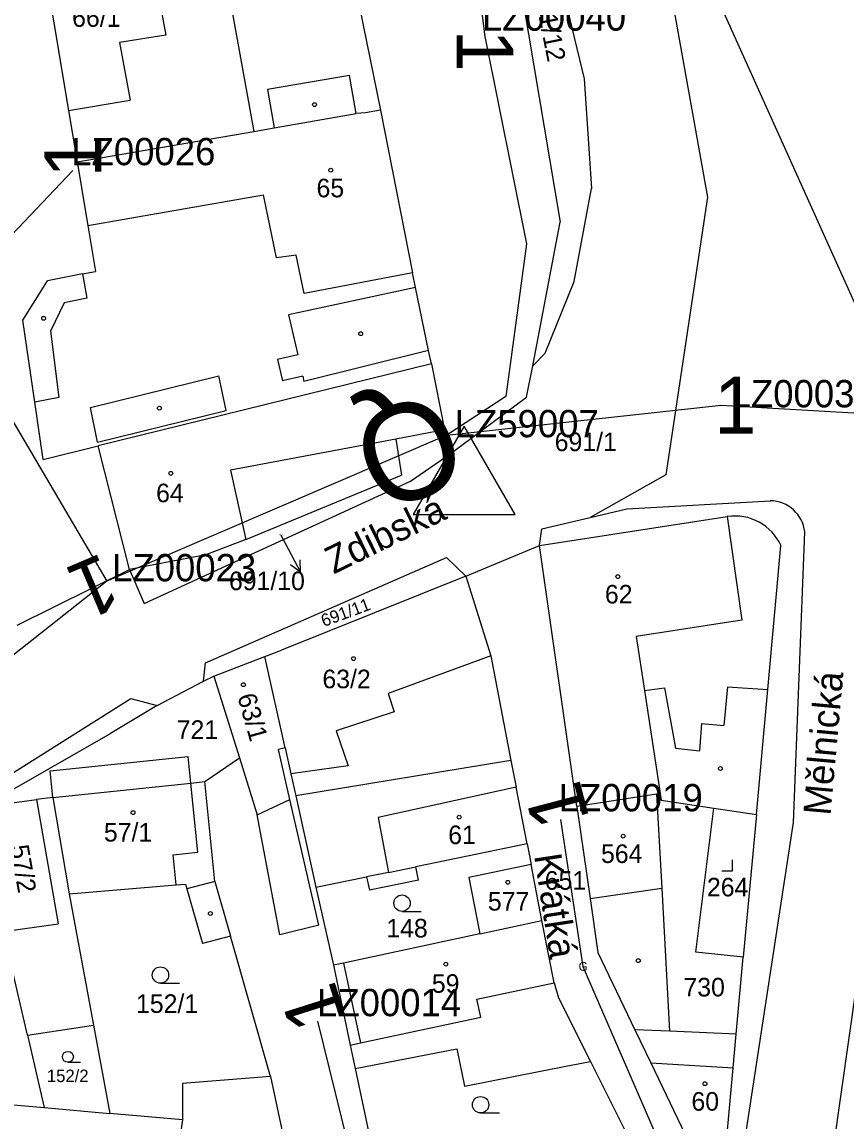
# Model space of a CAD drawing. Extents: x -738131 to -734179, y -1033447 to -1030078.
# Drawn here: x -736144.6 to -736069.2, y -1032267.7 to -1032166.9 of the extents above; entities that cross this region are included whole.
import ezdxf

# ---------------------------------------------------------------- set-up
doc = ezdxf.new("R2010")
doc.units = 0
for name, color, linetype in [('ftf_2010', 7, 'Continuous'), ('ftf_2050', 7, 'Continuous'), ('ftf_2080', 7, 'Continuous'), ('ftf_2240', 7, 'Continuous'), ('ftf_3010', 7, 'Continuous'), ('ftf_3010_ftf_3010_gtda_3015_gtda_3015_1', 7, 'Continuous'), ('ftf_3240', 7, 'Continuous'), ('ftf_3260', 7, 'Continuous'), ('ftf_3260_ftf_3260_gtda_3265_gtda_3265_1', 7, 'Continuous'), ('ftf_nu', 7, 'Continuous'), ('Vrstva 1', 7, 'Continuous'), ('Vrstva 2', 7, 'Continuous'), ('Vrstva 3', 7, 'Continuous'), ('Vrstva 4', 7, 'Continuous'), ('Vrstva 5', 7, 'Continuous'), ('Vrstva 7', 7, 'Continuous')]:
    doc.layers.add(name, color=color, linetype=linetype)

msp = doc.modelspace()

# ---------------------------------------------------------------- linework, layer by layer
at = {"layer": 'ftf_2010'}
for points in [[(-736107.59, -1032126.1), (-736102.25, -1032168.26)], [(-736102.25, -1032168.26), (-736098.43, -1032187.26), (-736100.35, -1032201.22), (-736105.73, -1032204.76)]]:
    msp.add_lwpolyline(points, dxfattribs=at)
at = {"layer": 'ftf_2050'}
for points in [[(-736169.66, -1032178.44), (-736151.73, -1032192.91), (-736136.87, -1032218.15)], [(-736139.99, -1032180.53), (-736151.73, -1032192.91)], [(-736105.73, -1032204.76), (-736080.61, -1032202.02)], [(-736080.61, -1032202.02), (-736059.51, -1032203.25)], [(-736136.87, -1032218.15), (-736162, -1032237.98)], [(-736095.33, -1032239.95), (-736093.27, -1032253.41), (-736082.77, -1032277.61)], [(-736117.59, -1032258.43), (-736105.13, -1032308.95)]]:
    msp.add_lwpolyline(points, dxfattribs=at)
at = {"layer": 'ftf_2080'}
msp.add_lwpolyline([(-736105.73, -1032204.76), (-736136.87, -1032218.15)], dxfattribs=at)
at = {"layer": 'ftf_2240'}
msp.add_lwpolyline([(-736108.82, -1032212.03), (-736099.47, -1032212.03), (-736104.14, -1032203.93)], close=True, dxfattribs=at)
at = {"layer": 'Vrstva 1'}
for points in [[(-736101.65, -1032147.92), (-736095.37, -1032185.27)], [(-736087.87, -1032149.39), (-736081.88, -1032182.97)], [(-736087.87, -1032149.39), (-736067.88, -1032193.8)], [(-736096.91, -1032156.59), (-736093.17, -1032172.14)], [(-736143.06, -1032158.95), (-736140.37, -1032175.05)], [(-736115.01, -1032159.26), (-736111.82, -1032175.01)], [(-736125.82, -1032163.63), (-736123.41, -1032176.95)], [(-736093.17, -1032172.14), (-736092.5, -1032182.19)], [(-736140.37, -1032175.05), (-736139.59, -1032179.75)], [(-736111.82, -1032175.01), (-736113.19, -1032175.26)], [(-736111.82, -1032175.01), (-736108.88, -1032189.89)], [(-736121.56, -1032176.63), (-736114.04, -1032175.33)], [(-736113.19, -1032175.26), (-736114.04, -1032175.33)], [(-736139.59, -1032179.75), (-736123.41, -1032176.95)], [(-736123.41, -1032176.95), (-736121.56, -1032176.63)], [(-736139.59, -1032179.75), (-736138.62, -1032185.57)], [(-736094.08, -1032190.71), (-736092.5, -1032182.19)], [(-736081.88, -1032182.97), (-736085.67, -1032208.4)], [(-736097.87, -1032198.41), (-736095.37, -1032185.27)], [(-736138.62, -1032185.57), (-736137.92, -1032189.77)], [(-736139.1, -1032190), (-736142.32, -1032190.63)], [(-736139.1, -1032190), (-736137.92, -1032189.77)], [(-736108.6, -1032191.24), (-736108.88, -1032189.89)], [(-736144.57, -1032194.23), (-736142.32, -1032190.63)], [(-736107.41, -1032197.01), (-736108.6, -1032191.24)], [(-736096.74, -1032197.25), (-736094.08, -1032190.71)], [(-736143.47, -1032201.74), (-736144.57, -1032194.23)], [(-736107.15, -1032198.24), (-736107.41, -1032197.01)], [(-736097.87, -1032198.41), (-736096.74, -1032197.25)], [(-736107.15, -1032198.24), (-736137.65, -1032205.75)], [(-736107.15, -1032198.24), (-736105.96, -1032204.29)], [(-736098.44, -1032201.3), (-736097.87, -1032198.41)], [(-736105.42, -1032206.49), (-736098.44, -1032201.3)], [(-736142.7, -1032207), (-736143.47, -1032201.74)], [(-736105.96, -1032204.29), (-736110.41, -1032205.12)], [(-736105.96, -1032204.29), (-736105.42, -1032206.49)], [(-736110.41, -1032205.12), (-736109.88, -1032208.43)], [(-736142.7, -1032207), (-736137.65, -1032205.75)], [(-736134.79, -1032217.08), (-736137.65, -1032205.75)], [(-736109.06, -1032208.99), (-736105.42, -1032206.49)], [(-736124.13, -1032214.32), (-736109.88, -1032208.43)], [(-736085.67, -1032208.4), (-736092.61, -1032212.3)], [(-736133.44, -1032220.19), (-736109.06, -1032208.99)], [(-736089.27, -1032211.52), (-736076.11, -1032210.77)], [(-736097.24, -1032214.86), (-736080.07, -1032212.23)], [(-736097.03, -1032213.33), (-736092.61, -1032212.3)], [(-736092.61, -1032212.3), (-736089.27, -1032211.52)], [(-736097.24, -1032214.86), (-736097.03, -1032213.33)], [(-736124.13, -1032214.32), (-736127.82, -1032215.73)], [(-736073.98, -1032240.24), (-736072.95, -1032213.63)], [(-736104, -1032217.69), (-736097.24, -1032214.86)], [(-736093.82, -1032238.76), (-736097.24, -1032214.86)], [(-736076.34, -1032228.05), (-736075.14, -1032214.9)], [(-736127.82, -1032215.73), (-736134.79, -1032217.08)], [(-736127.84, -1032225.62), (-736105.77, -1032215.97)], [(-736105.77, -1032215.97), (-736104, -1032217.69)], [(-736145.07, -1032222.16), (-736134.79, -1032217.08)], [(-736134.79, -1032217.08), (-736133.44, -1032220.19)], [(-736104, -1032217.69), (-736120.89, -1032224.44)], [(-736104, -1032217.69), (-736101.72, -1032224.97)], [(-736122.41, -1032225.03), (-736120.89, -1032224.44)], [(-736127.07, -1032226.83), (-736122.41, -1032225.03)], [(-736120.55, -1032233.41), (-736122.41, -1032225.03)], [(-736101.72, -1032224.97), (-736099.87, -1032234.55)], [(-736128.02, -1032227.3), (-736127.84, -1032225.62)], [(-736132.25, -1032229.51), (-736128.02, -1032227.3)], [(-736128.02, -1032227.3), (-736127.07, -1032226.83)], [(-736127.07, -1032226.83), (-736124.73, -1032234.32)], [(-736077.39, -1032239.5), (-736076.34, -1032228.05)], [(-736148.25, -1032237.42), (-736134.66, -1032228.89)], [(-736132.25, -1032229.51), (-736136.55, -1032232.07)], [(-736134.66, -1032228.89), (-736132.25, -1032229.51)], [(-736148.3, -1032238.81), (-736136.55, -1032232.07)], [(-736120.55, -1032233.41), (-736121.16, -1032233.54)], [(-736120.11, -1032238.12), (-736121.16, -1032233.54)], [(-736120.55, -1032233.41), (-736120.03, -1032235.78)], [(-736142.06, -1032235.49), (-736129.43, -1032234.18)], [(-736129.18, -1032236.62), (-736129.43, -1032234.18)], [(-736127.89, -1032236.49), (-736124.73, -1032234.32)], [(-736124.73, -1032234.32), (-736123.11, -1032239.52)], [(-736099.87, -1032234.55), (-736119.58, -1032237.8)], [(-736099.87, -1032234.55), (-736099.39, -1032237)], [(-736141.81, -1032237.93), (-736142.06, -1032235.49)], [(-736129.18, -1032236.62), (-736127.89, -1032236.49)], [(-736126.97, -1032245.64), (-736127.89, -1032236.49)], [(-736120.03, -1032235.78), (-736119.58, -1032237.8)], [(-736098.39, -1032242.2), (-736099.39, -1032237)], [(-736086.53, -1032237.64), (-736093.82, -1032238.76)], [(-736086.19, -1032237.59), (-736086.53, -1032237.64)], [(-736086.53, -1032237.64), (-736086.06, -1032246.26)], [(-736086.19, -1032237.59), (-736086.1, -1032238.18)], [(-736148.3, -1032238.81), (-736143.3, -1032238.13)], [(-736141.81, -1032237.93), (-736143.3, -1032238.13)], [(-736141.81, -1032237.93), (-736140.32, -1032246.76)], [(-736117.46, -1032249.62), (-736120.11, -1032238.12)], [(-736119.58, -1032237.8), (-736117.72, -1032246.17)], [(-736086.1, -1032238.18), (-736081.28, -1032238.91)], [(-736121.03, -1032250.52), (-736123.11, -1032239.52)], [(-736093.82, -1032238.76), (-736092.61, -1032247.19)], [(-736082.93, -1032252.1), (-736081.28, -1032238.91)], [(-736081.28, -1032238.91), (-736077.39, -1032239.5)], [(-736077.39, -1032239.5), (-736078.59, -1032252.55)], [(-736078.41, -1032269.16), (-736073.98, -1032240.24)], [(-736098.39, -1032242.2), (-736108.58, -1032244.29)], [(-736098.39, -1032242.2), (-736098.01, -1032244.09)], [(-736108.33, -1032245.51), (-736108.58, -1032244.29)], [(-736098.01, -1032244.09), (-736103.73, -1032245.27)], [(-736097.05, -1032249.22), (-736098.01, -1032244.09)], [(-736126.97, -1032245.64), (-736125.54, -1032250.64)], [(-736117.72, -1032246.17), (-736113.08, -1032245.21)], [(-736113.08, -1032245.21), (-736112.83, -1032246.44)], [(-736108.33, -1032245.51), (-736112.83, -1032246.44)], [(-736103.73, -1032245.27), (-736102.73, -1032250.44)], [(-736071.04, -1032274.99), (-736066.8, -1032245.12)], [(-736140.32, -1032246.76), (-736130.51, -1032245.94)], [(-736140.32, -1032246.76), (-736138.09, -1032258.78)], [(-736130.51, -1032245.94), (-736129.66, -1032245.87)], [(-736129.66, -1032245.87), (-736129.54, -1032246.3)], [(-736129.54, -1032246.3), (-736128.1, -1032251.31)], [(-736117.72, -1032246.17), (-736116.13, -1032253.31)], [(-736086.06, -1032246.26), (-736085.34, -1032259.35)], [(-736092.61, -1032247.19), (-736091.9, -1032252.15)], [(-736117.46, -1032249.62), (-736121.03, -1032250.52)], [(-736102.73, -1032250.44), (-736097.05, -1032249.22)], [(-736095.92, -1032254.9), (-736097.05, -1032249.22)], [(-736144.13, -1032259.71), (-736146.33, -1032250.2)], [(-736125.54, -1032250.64), (-736128.1, -1032251.31)], [(-736121.87, -1032263.48), (-736125.54, -1032250.64)], [(-736102.73, -1032250.44), (-736115.2, -1032253.12)], [(-736091.9, -1032252.15), (-736088.51, -1032259.22)], [(-736078.59, -1032252.55), (-736082.93, -1032252.1)], [(-736079.24, -1032259.61), (-736078.59, -1032252.55)], [(-736115.2, -1032253.12), (-736116.13, -1032253.31)], [(-736116.13, -1032253.31), (-736114.58, -1032260.61)], [(-736095.92, -1032254.9), (-736095.51, -1032256.29)], [(-736095.51, -1032256.29), (-736092.59, -1032262.11)], [(-736144.13, -1032259.71), (-736138.09, -1032258.78)], [(-736138.09, -1032258.78), (-736136.59, -1032266.88)], [(-736144.13, -1032259.71), (-736142.62, -1032266.34)], [(-736085.34, -1032259.35), (-736088.51, -1032259.22)], [(-736088.51, -1032259.22), (-736087.06, -1032262.23)], [(-736079.24, -1032259.61), (-736085.34, -1032259.35)], [(-736079.52, -1032262.7), (-736079.24, -1032259.61)], [(-736114.58, -1032260.61), (-736114.12, -1032262.77)], [(-736114.12, -1032262.77), (-736104.83, -1032260.97)], [(-736104.83, -1032260.97), (-736104.11, -1032264.38)], [(-736114.12, -1032262.77), (-736110.95, -1032277.74)], [(-736104.11, -1032264.38), (-736094.85, -1032262.56)], [(-736094.85, -1032262.56), (-736092.59, -1032262.11)], [(-736092.59, -1032262.11), (-736088.48, -1032270.29)], [(-736087.06, -1032262.23), (-736083.88, -1032268.86)], [(-736080.1, -1032269.07), (-736079.52, -1032262.7)], [(-736121.87, -1032263.48), (-736129.94, -1032264.13)], [(-736121.87, -1032263.48), (-736120.47, -1032270.07)], [(-736129.94, -1032264.13), (-736129.94, -1032267.47)], [(-736154.87, -1032265.25), (-736142.62, -1032266.34)], [(-736142.62, -1032266.34), (-736136.59, -1032266.88)], [(-736129.94, -1032267.47), (-736136.59, -1032266.88)], [(-736129.94, -1032267.47), (-736130.34, -1032270.1)]]:
    msp.add_lwpolyline(points, dxfattribs=at)
for centre, radius, start, end in [((-736076.18, -1032214.02), 3.25, 6.8547, 88.8511), ((-736079.36, -1032216.81), 4.64, 24.359, 98.7626)]:
    msp.add_arc(centre, radius, start, end, dxfattribs=at)
at = {"layer": 'Vrstva 3'}
for p, q in [((-736079.57, -1032244.66), (-736079.57, -1032243.66)), ((-736080.57, -1032244.66), (-736079.57, -1032244.66)), ((-736109.84, -1032248.37), (-736108.09, -1032248.37)), ((-736131.96, -1032254.95), (-736130.21, -1032254.95)), ((-736140.45, -1032262.19), (-736139.27, -1032262.19)), ((-736102.65, -1032266.83), (-736100.9, -1032266.83))]:
    msp.add_line(p, q, dxfattribs=at)
for centre, radius in [((-736109.84, -1032247.62), 0.75), ((-736131.96, -1032254.2), 0.75), ((-736140.44, -1032261.69), 0.503), ((-736102.65, -1032266.08), 0.75)]:
    msp.add_circle(centre, radius, dxfattribs=at)
at = {"layer": 'Vrstva 4'}
for points in [[(-736132.11, -1032164.65), (-736131.48, -1032168.13)], [(-736131.48, -1032168.13), (-736135.71, -1032168.81)], [(-736135.71, -1032168.81), (-736134.75, -1032174.08)], [(-736114.65, -1032171.83), (-736122.16, -1032173.11)], [(-736114.04, -1032175.33), (-736114.65, -1032171.83)], [(-736122.16, -1032173.11), (-736121.56, -1032176.63)], [(-736140.37, -1032175.05), (-736134.75, -1032174.08)], [(-736138.62, -1032185.57), (-736122.53, -1032182.75)], [(-736121.35, -1032188.53), (-736122.53, -1032182.75)], [(-736119.52, -1032188.28), (-736121.35, -1032188.53)], [(-736118.8, -1032191.81), (-736119.52, -1032188.28)], [(-736139.1, -1032190), (-736138.71, -1032192.22)], [(-736108.88, -1032189.89), (-736118.8, -1032191.81)], [(-736108.6, -1032191.24), (-736120.23, -1032193.76)], [(-736138.71, -1032192.22), (-736140.77, -1032192.64)], [(-736140.77, -1032192.64), (-736142.03, -1032195.25)], [(-736120.23, -1032193.76), (-736119.38, -1032197.41)], [(-736142.03, -1032195.25), (-736141.27, -1032201.32)], [(-736119.38, -1032197.41), (-736121.23, -1032197.84)], [(-736107.41, -1032197.01), (-736118.82, -1032199.85)], [(-736121.23, -1032197.84), (-736120.78, -1032199.79)], [(-736138.38, -1032202.22), (-736126.63, -1032199.33)], [(-736125.93, -1032202.51), (-736126.63, -1032199.33)], [(-736118.93, -1032199.36), (-736120.78, -1032199.79)], [(-736118.93, -1032199.36), (-736118.82, -1032199.85)], [(-736141.27, -1032201.32), (-736143.47, -1032201.74)], [(-736137.72, -1032205.41), (-736138.38, -1032202.22)], [(-736137.72, -1032205.41), (-736125.93, -1032202.51)], [(-736110.41, -1032205.12), (-736125.54, -1032207.98)], [(-736125.54, -1032207.98), (-736124.13, -1032214.32)], [(-736080.07, -1032212.23), (-736078.71, -1032221.72)], [(-736078.71, -1032221.72), (-736088.39, -1032223.2)], [(-736088.39, -1032223.2), (-736087.63, -1032228.16)], [(-736101.72, -1032224.97), (-736111.1, -1032228.43)], [(-736111.1, -1032228.43), (-736110.56, -1032230.09)], [(-736087.63, -1032228.16), (-736085.8, -1032227.89)], [(-736087.63, -1032228.16), (-736086.19, -1032237.59)], [(-736085.8, -1032227.89), (-736084.81, -1032233.43)], [(-736080.05, -1032227.8), (-736080.38, -1032231.36)], [(-736080.05, -1032227.8), (-736076.34, -1032228.05)], [(-736110.56, -1032230.09), (-736115.88, -1032231.84)], [(-736082.43, -1032231.17), (-736082.6, -1032233.68)], [(-736082.43, -1032231.17), (-736080.38, -1032231.36)], [(-736115.88, -1032231.84), (-736114.78, -1032235.06)], [(-736084.81, -1032233.43), (-736082.6, -1032233.68)], [(-736114.78, -1032235.06), (-736120.03, -1032235.78)], [(-736141.81, -1032237.93), (-736129.18, -1032236.62)], [(-736128.53, -1032242.95), (-736129.18, -1032236.62)], [(-736099.39, -1032237), (-736112.04, -1032239.77)], [(-736143.3, -1032238.13), (-736141.33, -1032249.52)], [(-736123.11, -1032239.52), (-736120.11, -1032238.12)], [(-736112.04, -1032239.77), (-736111.07, -1032244.8)], [(-736130.79, -1032243.18), (-736128.53, -1032242.95)], [(-736130.51, -1032245.94), (-736130.79, -1032243.18)], [(-736111.07, -1032244.8), (-736108.58, -1032244.29)], [(-736126.97, -1032245.64), (-736129.54, -1032246.3)], [(-736111.07, -1032244.8), (-736113.08, -1032245.21)], [(-736092.61, -1032247.19), (-736086.06, -1032246.26)], [(-736146.33, -1032250.2), (-736141.33, -1032249.52)], [(-736115.2, -1032253.12), (-736113.65, -1032260.42)], [(-736102.98, -1032256.4), (-736095.92, -1032254.9)], [(-736102.63, -1032258.07), (-736102.98, -1032256.4)], [(-736113.65, -1032260.42), (-736102.63, -1032258.07)], [(-736114.58, -1032260.61), (-736113.65, -1032260.42)], [(-736087.06, -1032262.23), (-736079.52, -1032262.7)]]:
    msp.add_lwpolyline(points, dxfattribs=at)
at = {"layer": 'Vrstva 5'}
for centre in [(-736117.86, -1032174.5), (-736116.37, -1032180.51), (-736142.66, -1032194.07), (-736113.62, -1032195.48), (-736132.06, -1032202.29), (-736131.01, -1032208.26), (-736090.08, -1032217.72), (-736114.29, -1032225.23), (-736124.37, -1032227.62), (-736080.69, -1032235.29), (-736134.47, -1032239.33), (-736104.61, -1032239.74), (-736089.59, -1032241.49), (-736100.15, -1032245.71), (-736127.39, -1032248.57), (-736088.21, -1032252.88), (-736105.83, -1032253.21), (-736082.1, -1032264.15)]:
    msp.add_circle(centre, 0.175, dxfattribs=at)
at = {"layer": 'Vrstva 7'}
for p, q in [((-736120.55, -1032214.65), (-736119.14, -1032217.3)), ((-736119.14, -1032217.3), (-736119.17, -1032216.18)), ((-736119.14, -1032217.3), (-736120.05, -1032216.65))]:
    msp.add_line(p, q, dxfattribs=at)
msp.add_lwpolyline([(-736120.93, -1032213.93), (-736120.55, -1032214.65)], dxfattribs=at)

# ---------------------------------------------------------------- texts
at = {"layer": 'ftf_3010'}
for rotation, p in [(270, (-736104.85, -1032167.62)), (90, (-736137.39, -1032181.18)), (203.0185, (-736137.29, -1032215.51)), (104.7548, (-736092.66, -1032239.91)), (107.648, (-736114.92, -1032258.26))]:
    msp.add_text('1', height=5.2, rotation=rotation, dxfattribs=at).set_placement(p)
msp.add_text('1', height=5.2, dxfattribs=at).set_placement((-736081.26, -1032204.62))
at = {"layer": 'ftf_3010_ftf_3010_gtda_3015_gtda_3015_1'}
for s, p in [('LZ00040', (-736102.52, -1032167.73)), ('LZ00026', (-736140.13, -1032180.05)), ('LZ00023', (-736136.39, -1032218.15)), ('LZ00019', (-736095.5, -1032239.21)), ('LZ00014', (-736117.62, -1032257.97))]:
    msp.add_text(s, height=2.5, rotation=0, dxfattribs=at).set_placement(p)
msp.add_text('LZ00030', height=2.5, dxfattribs=at).set_placement((-736079.75, -1032202.22))
at = {"layer": 'ftf_3240'}
msp.add_text('G', height=0.8, dxfattribs=at).set_placement((-736093.67, -1032253.81))
at = {"layer": 'ftf_3260'}
msp.add_text('Q', height=8.8, rotation=203.0215, dxfattribs=at).set_placement((-736106.73, -1032200.41))
at = {"layer": 'ftf_3260_ftf_3260_gtda_3265_gtda_3265_1'}
msp.add_text('LZ59007', height=2.5, dxfattribs=at).set_placement((-736105.02, -1032204.96))
at = {"layer": 'ftf_nu'}
for s, rotation, p in [('Zdibská', 26.1415, (-736116.1, -1032217.53)), ('Mělnická', 84.8145, (-736070.61, -1032239.65)), ('Krátká', 278.7559, (-736097.75, -1032243.26))]:
    msp.add_text(s, height=2.5, rotation=rotation, dxfattribs=at).set_placement(p)
at = {"layer": 'Vrstva 2'}
for s, height, rotation, p in [('691/12', 1.7, 281.3099, (-736097.85, -1032163.87)), ('691/11', 1.14, 20.3392, (-736117, -1032222.34)), ('63/1', 1.7, 285.7443, (-736124.93, -1032228.67)), ('57/2', 1.7, 279.7737, (-736145.73, -1032242.42))]:
    msp.add_text(s, height=height, rotation=rotation, dxfattribs=at).set_placement(p)
for s, height, p in [('66/1', 1.7, (-736140.05, -1032167.38)), ('65', 1.7, (-736117.67, -1032182.99)), ('691/1', 1.7, (-736095.86, -1032206.23)), ('64', 1.7, (-736132.36, -1032210.91)), ('691/10', 0.1, (-736121.11, -1032213.93)), ('62', 1.7, (-736091.26, -1032220.18)), ('63/2', 1.7, (-736117.13, -1032227.94)), ('721', 1.7, (-736130.47, -1032232.58)), ('57/1', 1.7, (-736137.14, -1032241.98)), ('61', 1.7, (-736105.61, -1032242.21)), ('564', 1.7, (-736091.62, -1032243.94)), ('651', 1.7, (-736096.77, -1032246.39)), ('264', 1.7, (-736081.92, -1032247)), ('577', 1.7, (-736101.98, -1032248.3)), ('148', 1.7, (-736111.28, -1032250.76)), ('59', 1.7, (-736107.11, -1032255.83)), ('730', 1.7, (-736084.07, -1032256.16)), ('152/1', 1.7, (-736134.2, -1032257.67)), ('152/2', 1.14, (-736142.36, -1032264)), ('60', 1.7, (-736083.34, -1032266.62))]:
    msp.add_text(s, height=height, dxfattribs=at).set_placement(p)
at = {"layer": 'Vrstva 7'}
msp.add_text('691/10', height=1.7, dxfattribs=at).set_placement((-736125.69, -1032218.96))

doc.saveas('drawing.dxf')
